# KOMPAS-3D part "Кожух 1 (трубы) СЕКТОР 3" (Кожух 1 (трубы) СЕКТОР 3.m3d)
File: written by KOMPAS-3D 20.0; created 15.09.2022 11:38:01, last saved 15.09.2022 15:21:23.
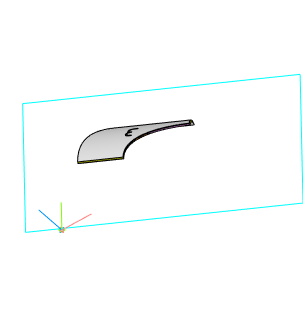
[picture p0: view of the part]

Document properties: Полное имя файла: D:\YAKOVLEV\ПРОЕКТЫ\ДЦ-2. ДП-7 Газопровод Окожушивание\ПРОБА Соединение труб. Окожушивание\Кожух 1 (трубы) СЕКТОР 3.m3d

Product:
- Part/product: Кожух 1 (трубы) СЕКТОР 3
    Материал: Сталь 45  ГОСТ 1050-2013 (density 7810 kg/m3)
    Масса: 116.573

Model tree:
1. Эскиз:1  (with: Обечайка:1)  (labels: Кожух 1 (трубы))
2. Обечайка:1  (labels: Кожух 1 (трубы))
     Расстояние 1 = -2450; Смещение 1 = -50; Толщина листового тела = 20
3. Сгиб(1) - Обечайка:1
     Радиус сгиба = 980; Коэффициент = 0.4; Величина сгиба = 10; Зазор = 1
4. Касательная плоскость:1  (with: Обечайка:1)
5. Эскиз:2  (with: Обечайка:1)  (labels: Кожух 1 (трубы))
6. Вырез в листовом теле:2
     Глубина выреза = 2400
7. Разогнуть:1  (with: Обечайка:1)
8. Эскиз:3  (with: Обечайка:1, Вырез в листовом теле:2)
9. Вырез в листовом теле:3
     Глубина выреза = 1000
10. Эскиз:4  (with: Обечайка:1, Вырез в листовом теле:2, Вырез в листовом теле:3)
11. Вырез в листовом теле:4
     Глубина выреза = 1000
12. Эскиз:5  (with: Обечайка:1, Вырез в листовом теле:3, Вырез в листовом теле:4)
13. Вырез в листовом теле:5
     Глубина выреза = 10
14. Фаска:1  (with: Вырез в листовом теле:2, Вырез в листовом теле:3, Вырез в листовом теле:4)
     Угол = 45; Длина 1 = 3; Длина 2 = 3
15. Эскиз:6  (with: Вырез в листовом теле:5)
16. Вырез в листовом теле:6
     Глубина выреза = 1000
17. Эскиз:7  (with: Обечайка:1)
18. Вырез в листовом теле:7
     Глубина выреза = 0.1
19. Фаска:2  (with: Вырез в листовом теле:6)
     Угол = 20; Длина 1 = 18; Длина 2 = 6.55146
20. Фаска:3  (with: Вырез в листовом теле:4, Вырез в листовом теле:2, Вырез в листовом теле:3)
     Угол = 45; Длина 1 = 5; Длина 2 = 5
21. Согнуть:1  (with: Обечайка:1)
22. Развертка  (labels: Сталь 45  ГОСТ 1050-2013)

Expressions: v140*2
Referenced files in D:\YAKOVLEV\ПРОЕКТЫ\ДЦ-2. ДП-7 Газопровод Окожушивание\ПРОБА Соединение труб. Окожушивание\: Соединение труб. Окожушивание -2.a3d
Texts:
  Соединение труб. Окожушивание\Труба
